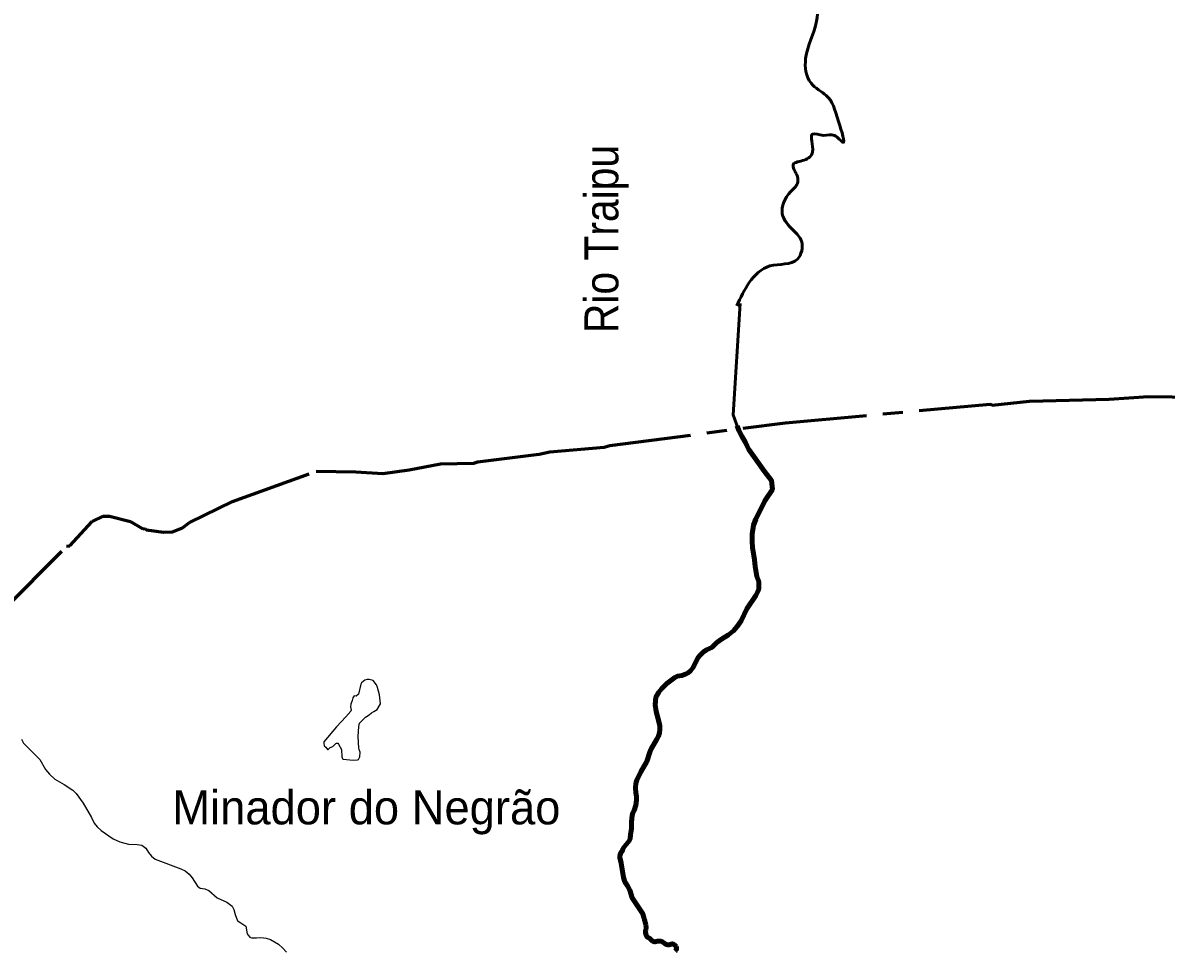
# Model space of a CAD drawing. Extents: x 553962 to 842807, y 8883888 to 9032388.
# Drawn here: x 729677 to 746538, y 8967044 to 8980740 of the extents above; entities that cross this region are included whole.
import ezdxf
from ezdxf.enums import TextEntityAlignment as Align

# ---------------------------------------------------------------- set-up
doc = ezdxf.new("R2010")
doc.units = 0
doc.header["$LTSCALE"] = 200
doc.linetypes.add('LONG_DASH_SHORT_DASH', pattern=[9.9, 6, -1.2, 1.5, -1.2])
for name, color, linetype, lineweight in [('21', 7, 'Continuous', 25), ('24', 7, 'Continuous', 25), ('7', 7, 'LONG_DASH_SHORT_DASH', 60), ('9', 7, 'Continuous', 90)]:
    doc.layers.add(name, color=color, linetype=linetype, lineweight=lineweight)
doc.layers.add('41', color=7, linetype='Continuous')
doc.layers.add('49', color=7, linetype='Continuous')

msp = doc.modelspace()

# ---------------------------------------------------------------- linework, layer by layer
at = {"layer": '21'}
for points in [[(734441.2, 8970498.9), (734303.8, 8970355.7), (734116.5, 8970129.9), (734113.1, 8970114.7), (734119.4, 8970075.5), (734145.2, 8970051.2), (734168.9, 8970019.5), (734181.4, 8970021.5), (734206.5, 8970050.8), (734247.2, 8970065.8), (734290.4, 8970107.4), (734303.5, 8970111.7), (734321.8, 8970111.1), (734333.6, 8970097.9), (734375, 8970020.5), (734381.7, 8969909.7), (734389.7, 8969884.2), (734396.2, 8969874.8), (734551.2, 8969860.5), (734613.7, 8969866.7), (734627.4, 8969872.6), (734648.3, 8969912.4), (734649.6, 8969980.8), (734634.3, 8970019.7), (734630.8, 8970039.7), (734623.8, 8970209), (734629.4, 8970357.2), (734643.8, 8970405.7), (734658.9, 8970427.2), (734730.6, 8970496.3), (734782.1, 8970530.8), (734817.5, 8970561.3), (734855.2, 8970579.8), (734904.2, 8970611.7), (734951.1, 8970691.3), (734935.8, 8970827.7), (734908.4, 8970936.3), (734891.3, 8970974.5), (734841.3, 8971037.1), (734782.7, 8971051.2)], [(734782.7, 8971051.2), (734756.2, 8971050.8), (734720.8, 8971040.1), (734672, 8971001.4), (734663.3, 8970981.6), (734624.9, 8970837.4), (734592.1, 8970806.3), (734562.4, 8970812), (734543.6, 8970783.7), (734532, 8970740.5), (734512.6, 8970689.2), (734508.8, 8970650.1), (734519.5, 8970599.8), (734514.8, 8970584.3), (734441.2, 8970498.9)]]:
    msp.add_lwpolyline(points, dxfattribs=at)
at = {"layer": '24', "lineweight": 53}
for points in [[(740256.1, 8976602), (740150, 8974957.6), (740199.7, 8974820.8)], [(740199.7, 8974820.8), (740238.1, 8974727.3), (740279.6, 8974643.7), (740334, 8974546.8), (740357.2, 8974493.5), (740382.9, 8974446.8), (740484.1, 8974309.5), (740613.7, 8974119.1), (740717.4, 8973990.4), (740732.3, 8973856.4), (740732.3, 8973856.4), (740732.3, 8973856.4), (740732.3, 8973856.4), (740618, 8973688.2), (740487, 8973417.6), (740453.4, 8973331.1), (740434.4, 8973194.5), (740433.5, 8973090.3), (740439.6, 8973000.5), (740466.4, 8972816.9), (740475.8, 8972719.9), (740503, 8972572.4), (740529.6, 8972497.6), (740528.8, 8972385.3), (740511.7, 8972342.2), (740484.3, 8972292.1), (740351.8, 8972095.1), (740271.5, 8971918), (740212.1, 8971832.2), (740155.8, 8971771.6), (740084.9, 8971712.7), (739981.4, 8971647.3), (739910.7, 8971596.4), (739837.5, 8971524.6), (739757.3, 8971490.6), (739708.7, 8971453.2), (739664.3, 8971410.8), (739632.6, 8971371.3), (739561.2, 8971230.5), (739523.3, 8971179.7), (739487, 8971150), (739449.3, 8971129.7), (739395.4, 8971112.6), (739333.7, 8971101.4), (739290.2, 8971081), (739173.2, 8970993.1), (739094.9, 8970916.4), (739054.2, 8970867.5), (739009.7, 8970790), (739003.8, 8970676.8), (739015.8, 8970579.9), (739051.5, 8970450.1), (739063.7, 8970387.4), (739071.4, 8970367.8), (739072.7, 8970313.5), (739066, 8970263.1), (739051.2, 8970216.4), (739028.1, 8970169.5), (738938.6, 8970019), (738921.2, 8969978.8), (738878.8, 8969842.3), (738791.5, 8969691.8), (738791.5, 8969691.8), (738733.8, 8969568.4), (738716.4, 8969521.7)], [(738716.4, 8969521.7), (738712.1, 8969454.1), (738717.3, 8969381.7), (738726.3, 8969324), (738727.4, 8969273.7), (738715.5, 8969198), (738691.5, 8969119), (738673.7, 8969086.8), (738662.6, 8969043.4), (738652.4, 8968953.5), (738651, 8968849.4), (738637.2, 8968762.8), (738633.9, 8968702.3), (738619.6, 8968671), (738536.5, 8968568.4), (738527.1, 8968550.9), (738521.9, 8968529), (738494.8, 8968495.2), (738481.7, 8968447.9), (738480.1, 8968427.4), (738500, 8968342), (738533.5, 8968133), (738555.2, 8968065.6), (738596.3, 8968005.9), (738628.6, 8967942.3), (738661.9, 8967831), (738818, 8967592.6), (738830.4, 8967556.3)], [(738830.4, 8967556.3), (738834.2, 8967542.6), (738837.7, 8967529), (738840.7, 8967516.2), (738845.7, 8967504.7), (738849.9, 8967492.5), (738850.3, 8967483.6), (738854.3, 8967471.6), (738857.7, 8967458), (738859.7, 8967445.1), (738862.7, 8967432.6), (738865.9, 8967420), (738868.8, 8967405.2), (738868.9, 8967391.8), (738868.2, 8967379), (738865.1, 8967366.3), (738862, 8967353.6), (738859.3, 8967339.4), (738859.3, 8967326.5), (738859.7, 8967313.1), (738863.5, 8967298.8), (738867.7, 8967286), (738870.9, 8967270.3), (738877.9, 8967259.2), (738887.8, 8967249.3), (738899.7, 8967242.8), (738913.1, 8967239.5), (738924.4, 8967232.4), (738934.7, 8967222.3), (738944.1, 8967212.4), (738954.2, 8967202), (738965.1, 8967192.5), (738977.1, 8967186.1), (738992.3, 8967182), (739005.7, 8967183.8), (739018.2, 8967186.9), (739031.3, 8967189.7), (739044.9, 8967190.6), (739058.1, 8967190.6), (739071.4, 8967190.6), (739084.6, 8967190), (739098.8, 8967187.9), (739114.9, 8967178.8), (739126, 8967171), (739135.5, 8967162.6), (739146.5, 8967154.6), (739156.7, 8967146), (739168.6, 8967140), (739183.1, 8967137.6), (739195.8, 8967137.5), (739209, 8967138.7), (739223, 8967141.7), (739237, 8967146.4), (739250.3, 8967150.8), (739263.6, 8967149.5), (739275.9, 8967143.1), (739287.3, 8967135.2), (739296.8, 8967126.4), (739304.9, 8967116.7), (739309.3, 8967110.9)], [(739309.3, 8967110.9), (739317.7, 8967092.1), (739317.8, 8967077.7), (739313.7, 8967065.7), (739305.1, 8967055.2), (739299.2, 8967042.7)]]:
    msp.add_lwpolyline(points, dxfattribs=at)
at = {"layer": '24'}
msp.add_lwpolyline([(729657.8, 8970174.1), (729686.6, 8970110.8), (729928.3, 8969870.5), (730012.4, 8969726.4), (730069.7, 8969653.9), (730149.2, 8969579.5), (730284.8, 8969503.9), (730412, 8969418.7), (730463.2, 8969367.6), (730567.7, 8969229.8), (730688.7, 8969016.5), (730730.3, 8968933.7), (730772.2, 8968877.4), (730829.8, 8968823.3), (731008.2, 8968703.6), (731105.3, 8968654.8), (731233, 8968624.6), (731360.6, 8968619.3), (731432.2, 8968607.5), (731490.4, 8968564.6), (731529, 8968498.9), (731572, 8968444.1), (731629.2, 8968401.6), (732006.1, 8968259.5), (732068.7, 8968231.4), (732130.1, 8968177.5), (732172.3, 8968124.3), (732254.1, 8968003.8), (732270.8, 8967986), (732292.3, 8967973.5), (732359.4, 8967962.3), (732419.1, 8967940.3), (732541.4, 8967832.4), (732686.6, 8967768.5), (732762.4, 8967705.5), (732787.2, 8967659.9), (732807.8, 8967584.8), (732842.4, 8967493.1), (732851.1, 8967484), (732892.3, 8967462.8), (732967.3, 8967414.9), (732986, 8967300), (732997.8, 8967278.1), (733022.8, 8967248.5), (733047.5, 8967241.4), (733120.3, 8967238.6), (733188.8, 8967243.5), (733264.7, 8967233.7), (733328, 8967214.7), (733447.7, 8967146.1), (733512.9, 8967086.8), (733564.5, 8967027.4)], dxfattribs=at)
msp.add_spline([(715037, 8973071.8), (715705.1, 8973746.2), (715968.5, 8974273.5), (716313.1, 8974881.9), (716799.5, 8975226.6), (717083.2, 8975429.4), (717285.9, 8975328), (717752, 8975003.5), (717934.4, 8974821), (718137.1, 8974800.7), (718522.2, 8975145.5), (718826.2, 8975165.8), (718927.5, 8975307.7), (719251.8, 8975287.5), (719596.3, 8975855.3), (719799, 8976301.5), (720042.2, 8976686.8), (720771.8, 8977072.1), (721197.4, 8977051.8), (721481.2, 8977356), (721987.8, 8977396.6), (722291.8, 8977356), (722514.8, 8977639.9), (722859.3, 8978086.1), (723244.4, 8978309.2), (723548.4, 8978795.9), (723507.9, 8979566.5), (723426.8, 8979749.1), (723730.8, 8980235.8), (724115.9, 8980418.3), (724501, 8980803.6), (724886, 8981067.2), (724886, 8981594.5), (724865.8, 8981939.3), (725068.4, 8982385.5), (725169.8, 8982831.6), (725331.9, 8983216.9), (725311.6, 8983582), (725473.8, 8983825.3), (725696.7, 8983987.6), (725777.8, 8984433.7), (725858.8, 8984636.5), (726183.1, 8984636.5), (726162.8, 8984920.5), (726284.5, 8985163.8), (726588.5, 8985569.4), (726993.8, 8986056.1), (726770.9, 8986299.5), (726466.9, 8986238.7), (726264.2, 8986340.1), (726527.7, 8986563.1), (726487.1, 8986745.7), (726770.9, 8986907.9), (727155.9, 8987090.4), (727297.8, 8987171.5), (727338.3, 8987496), (727581.6, 8987698.8), (727743.7, 8987921.9), (727905.8, 8988084.1), (728068, 8988408.6), (728351.7, 8988510), (728453, 8988814.2), (728655.7, 8988854.8), (728676, 8989098.1), (728898.9, 8989260.4), (729121.8, 8989260.4), (729284, 8989037.3), (729527.2, 8988733.1), (729750.1, 8988712.8), (729973.1, 8988834.5), (729993.3, 8988753.4), (730054.1, 8988530.3), (730135.2, 8988469.4), (730358.1, 8988469.4), (730459.5, 8988408.6), (730702.7, 8988489.7), (730702.7, 8988611.4), (730885.1, 8988652), (731067.5, 8988469.4), (731168.8, 8988347.8), (731472.8, 8988368), (731736.3, 8988631.7), (731857.9, 8988834.5), (732222.7, 8988814.2), (732324, 8989017), (732506.4, 8989138.7), (732547, 8989300.9), (732851, 8989402.3), (733073.9, 8989382), (733114.4, 8989666), (733215.8, 8989848.5)], degree=3, dxfattribs=at)
at = {"layer": '24', "lineweight": 53}
msp.add_spline([(740207.8, 8976565.1), (740390.3, 8976909.9), (740694.3, 8977153.2), (741099.6, 8977254.6), (741160.4, 8977518.3), (741038.8, 8977680.5), (740876.7, 8977923.9), (740998.3, 8978248.3), (741099.6, 8978370), (741099.6, 8978471.4), (741038.8, 8978653.9), (741200.9, 8978714.8), (741322.5, 8978836.5), (741322.5, 8979100.1), (741484.7, 8979079.8), (741646.8, 8979079.8), (741768.4, 8978978.4), (741707.6, 8979282.6), (741525.2, 8979667.9), (741302.3, 8979850.5), (741221.2, 8980215.5), (741383.3, 8980763.1), (741383.3, 8981209.2), (741383.3, 8981432.3), (741991.3, 8982770.8), (742356.2, 8983723.9), (742417, 8984271.5), (742741.2, 8985042.1), (742903.4, 8985812.8), (743106, 8986218.4), (743470.8, 8986380.6), (743734.3, 8986887.6), (743734.3, 8987354.1), (744038.3, 8987354.1), (744322.1, 8987658.2), (744342.3, 8987881.3), (744524.7, 8988145), (744686.9, 8988266.7), (744849, 8988408.6), (745031.4, 8988347.8), (745274.6, 8988205.8), (745416.5, 8988205.8), (745598.9, 8988388.3), (745659.7, 8988631.7)], degree=3, dxfattribs=at)
at = {"layer": '7'}
for points in [[(729404.2, 8972096.7), (730321.7, 8973018.8), (730368.4, 8973026), (730699.4, 8973383.6), (730862, 8973459.9), (730956.1, 8973460), (731265.8, 8973385.6), (731447.8, 8973274.4), (731473.6, 8973278.5), (731501.8, 8973259.3), (731752.1, 8973224.9), (731885.4, 8973232.8), (732033.3, 8973290.9), (732132.7, 8973369.8), (732767.6, 8973679.2), (734004.4, 8974123.6), (734587.5, 8974117.1), (734986.3, 8974093.8), (735372.7, 8974147.2), (735835.4, 8974235.1), (736327.4, 8974244.9), (736385.3, 8974265.2), (737292.2, 8974376.7), (737450.9, 8974411), (738250.7, 8974481.5), (738334.6, 8974505.4), (740923.3, 8974839.9), (743944.6, 8975116), (743973.3, 8975101.7), (744524.3, 8975159.5), (745697.7, 8975189)], [(745697.7, 8975189), (745697.7, 8975189), (746278.3, 8975226), (747060.9, 8975214.3)]]:
    msp.add_lwpolyline(points, dxfattribs=at)
at = {"layer": '9'}
for points in [[(740210.1, 8974795.4), (740238.1, 8974727.3), (740279.6, 8974643.7), (740334, 8974546.8), (740357.2, 8974493.5), (740382.9, 8974446.8), (740484.1, 8974309.5), (740613.7, 8974119.1), (740717.4, 8973990.4), (740732.3, 8973856.4), (740732.3, 8973856.4), (740732.3, 8973856.4), (740732.3, 8973856.4), (740618, 8973688.2), (740487, 8973417.6), (740453.4, 8973331.1), (740434.4, 8973194.5), (740433.5, 8973090.3), (740439.6, 8973000.5), (740466.4, 8972816.9), (740475.8, 8972719.9), (740503, 8972572.4), (740529.6, 8972497.6), (740528.8, 8972385.3), (740511.7, 8972342.2), (740484.3, 8972292.1), (740351.8, 8972095.1), (740271.5, 8971918), (740212.1, 8971832.2), (740155.8, 8971771.6), (740084.9, 8971712.7), (739981.4, 8971647.3), (739910.7, 8971596.4), (739837.5, 8971524.6), (739757.3, 8971490.6), (739708.7, 8971453.2), (739664.3, 8971410.8), (739632.6, 8971371.3), (739561.2, 8971230.5), (739523.3, 8971179.7), (739487, 8971150), (739449.3, 8971129.7), (739395.4, 8971112.6), (739333.7, 8971101.4), (739290.2, 8971081), (739173.2, 8970993.1), (739094.9, 8970916.4), (739054.2, 8970867.5), (739009.7, 8970790), (739003.8, 8970676.8), (739015.8, 8970579.9), (739051.5, 8970450.1), (739063.7, 8970387.4), (739071.4, 8970367.8), (739072.7, 8970313.5), (739066, 8970263.1), (739051.2, 8970216.4), (739028.1, 8970169.5), (738938.6, 8970019), (738921.2, 8969978.8), (738878.8, 8969842.3), (738791.5, 8969691.8), (738791.5, 8969691.8), (738733.8, 8969568.4), (738716.4, 8969521.7)], [(738716.4, 8969521.7), (738712.1, 8969454.1), (738717.3, 8969381.7), (738726.3, 8969324), (738727.4, 8969273.7), (738715.5, 8969198), (738691.5, 8969119), (738673.7, 8969086.8), (738662.6, 8969043.4), (738652.4, 8968953.5), (738651, 8968849.4), (738637.2, 8968762.8), (738633.9, 8968702.3), (738619.6, 8968671), (738536.5, 8968568.4), (738527.1, 8968550.9), (738521.9, 8968529), (738494.8, 8968495.2), (738481.7, 8968447.9), (738480.1, 8968427.4), (738500, 8968342), (738533.5, 8968133), (738555.2, 8968065.6), (738596.3, 8968005.9), (738628.6, 8967942.3), (738661.9, 8967831), (738818, 8967592.6), (738830.4, 8967556.3)], [(738830.4, 8967556.3), (738834.2, 8967542.6), (738837.7, 8967529), (738840.7, 8967516.2), (738845.7, 8967504.7), (738849.9, 8967492.5), (738850.3, 8967483.6), (738854.3, 8967471.6), (738857.7, 8967458), (738859.7, 8967445.1), (738862.7, 8967432.6), (738865.9, 8967420), (738868.8, 8967405.2), (738868.9, 8967391.8), (738868.2, 8967379), (738865.1, 8967366.3), (738862, 8967353.6), (738859.3, 8967339.4), (738859.3, 8967326.5), (738859.7, 8967313.1), (738863.5, 8967298.8), (738867.7, 8967286), (738870.9, 8967270.3), (738877.9, 8967259.2), (738887.8, 8967249.3), (738899.7, 8967242.8), (738913.1, 8967239.5), (738924.4, 8967232.4), (738934.7, 8967222.3), (738944.1, 8967212.4), (738954.2, 8967202), (738965.1, 8967192.5), (738977.1, 8967186.1), (738992.3, 8967182), (739005.7, 8967183.8), (739018.2, 8967186.9), (739031.3, 8967189.7), (739044.9, 8967190.6), (739058.1, 8967190.6), (739071.4, 8967190.6), (739084.6, 8967190), (739098.8, 8967187.9), (739114.9, 8967178.8), (739126, 8967171), (739135.5, 8967162.6), (739146.5, 8967154.6), (739156.7, 8967146), (739168.6, 8967140), (739183.1, 8967137.6), (739195.8, 8967137.5), (739209, 8967138.7), (739223, 8967141.7), (739237, 8967146.4), (739250.3, 8967150.8), (739263.6, 8967149.5), (739275.9, 8967143.1), (739287.3, 8967135.2), (739296.8, 8967126.4), (739304.9, 8967116.7), (739309.3, 8967110.9)], [(739309.3, 8967110.9), (739317.7, 8967092.1), (739317.8, 8967077.7), (739313.7, 8967065.7), (739305.1, 8967055.2), (739299.2, 8967042.7)]]:
    msp.add_lwpolyline(points, dxfattribs=at)

# ---------------------------------------------------------------- texts
at = {"layer": '41'}
msp.add_text('Minador do Negrão', height=500, dxfattribs=at).set_placement((731880.7, 8968914.6))
at = {"layer": '49', "width": 0.9}
msp.add_text('Rio Traipu', height=500, rotation=90, dxfattribs=at).set_placement((738459.1, 8977551.3), align=Align.CENTER)

doc.saveas('drawing.dxf')
